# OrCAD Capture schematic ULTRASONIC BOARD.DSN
size A
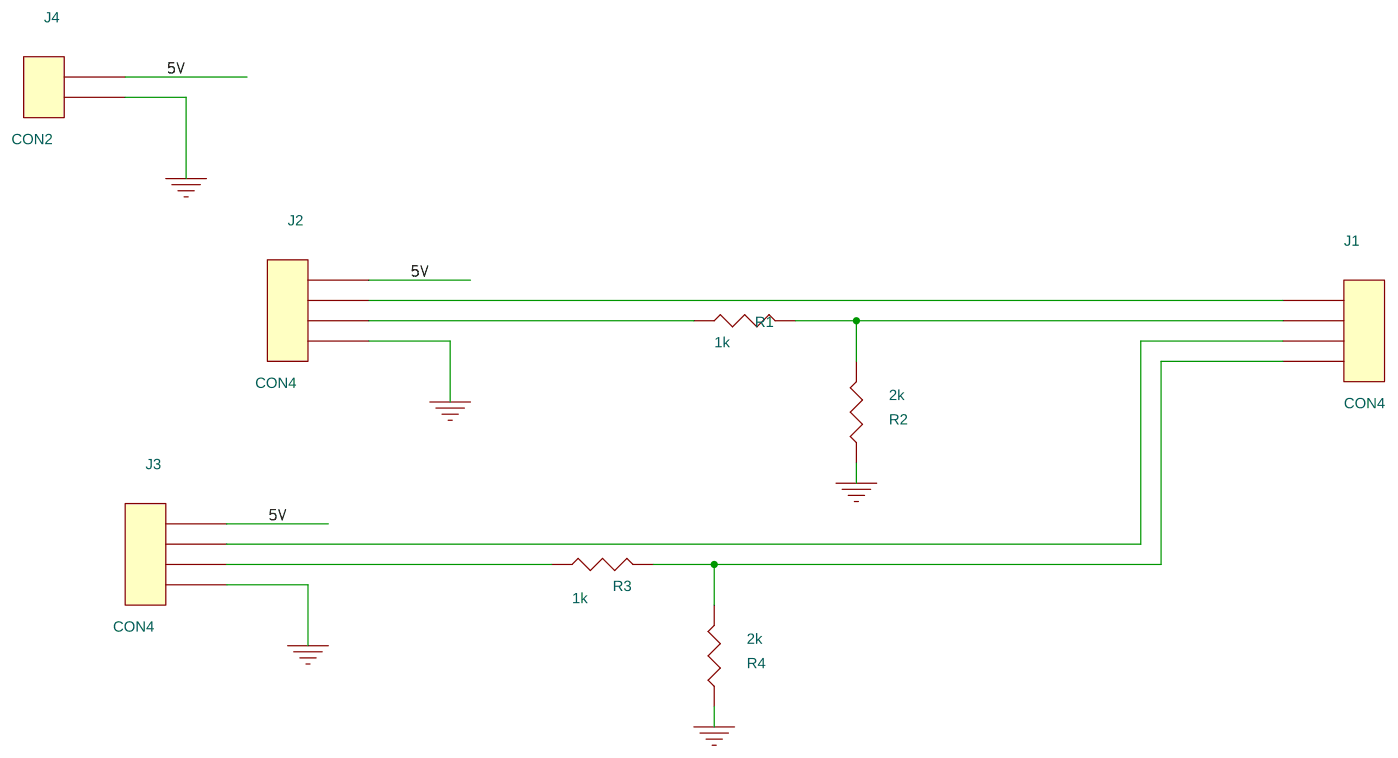
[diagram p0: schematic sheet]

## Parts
J1  CON4  [GU-MOLEX4]
J2  CON4  [GU-MOLEX4]
J3  CON4  [GU-MOLEX4]
J4  CON2  [GU-MOLEX2]
R1  1k  [GU-RC400]
R2  2k  [GU-RC400]
R3  1k  [GU-RC400]
R4  2k  [GU-RC400]

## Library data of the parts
J1-J3 = CON4
J4 = CON2
R1-R4 = R

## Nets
5V: J2.1 J3.1 J4.1
GND: J2.4 J3.4 J4.2 R2.2 R4.2
N00132: J1.1 J2.2
N00136: J2.3 R1.1
N00189: J1.2 R1.2 R2.1
N00349: J1.3 J3.2
N00369: J3.3 R3.1
N00373: J1.4 R3.2 R4.1
